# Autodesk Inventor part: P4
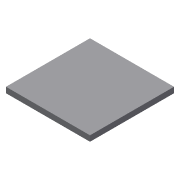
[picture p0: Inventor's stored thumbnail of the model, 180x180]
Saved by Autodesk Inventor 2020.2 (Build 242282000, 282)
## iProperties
Created: 2005-11
Part Number: P4
Document SubType Name: Modeling
Designer: F.Stasiak
Material: Ogólny
Density: 1 g/cm^3
Appearance: Domyślna
Manager: www.cadconsulting.pl
Company: Fabian Stasiak CAD Consulting
Author: F.Stasiak
Subject: Zbiór ćwiczeń. Autodesk Inventor 2020. Kurs podstawowy
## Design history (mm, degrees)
sketch "Szkic1"
  geometry: L1 (75, 75)-(75, -75); L2 (75, -75)-(-75, -75); L3 (-75, -75)-(-75, 75); L4 (-75, 75)-(75, 75); 2 further points
  constraints: 8 end point, 1 coincident, 7 other
  dimensions: "d0" = 150 distance of L1.end L2.end
extrude "Wyciągnięcie proste1" new body sketch "Szkic1" distance "d1" = 10; taper "d2" = 0 deg
node "Bryła1"
node "Korpusy bryłowe"
node "Korpusy powierzchniowe"
